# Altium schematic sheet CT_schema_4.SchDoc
size 312 x 238 mm
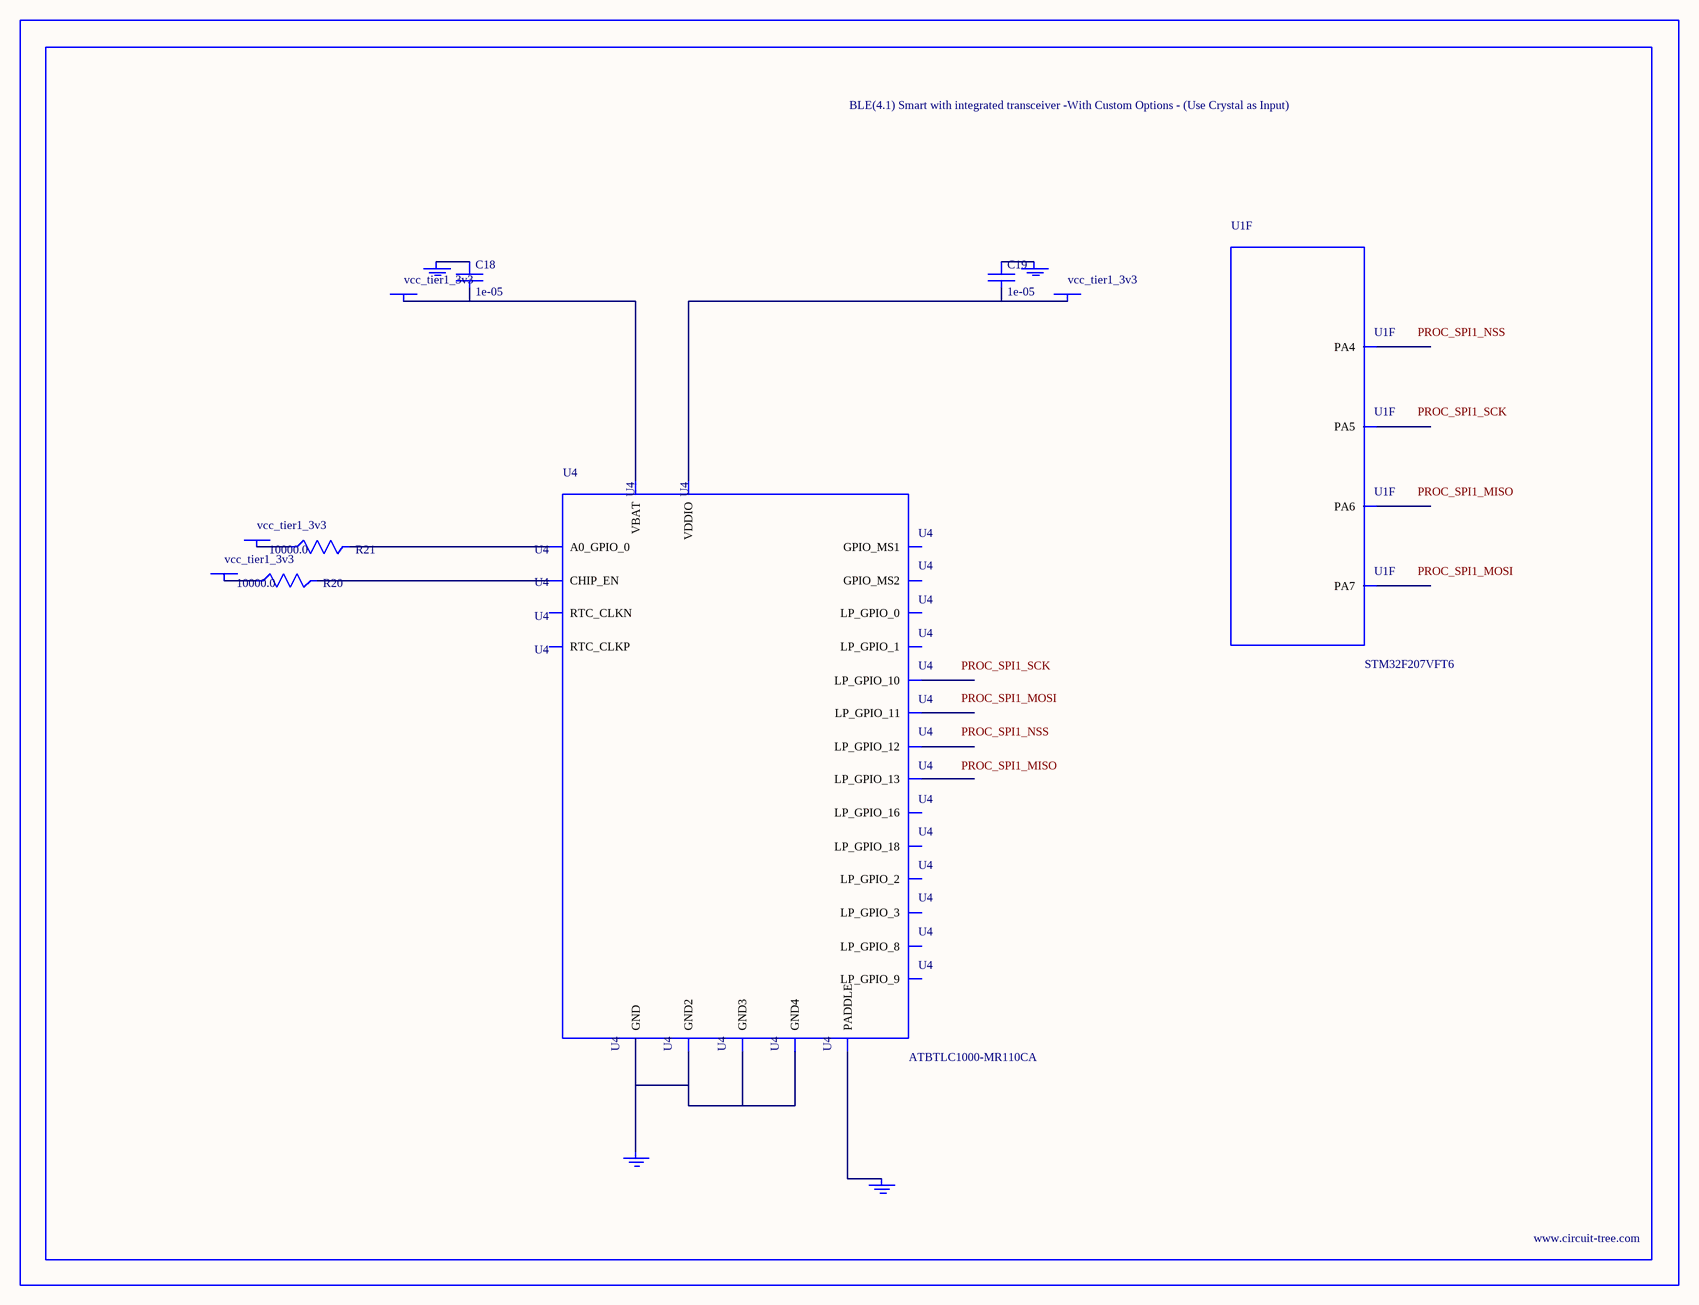
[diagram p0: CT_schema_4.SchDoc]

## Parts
BORDER3  (no value)
C18  1e-05  [C0805]
C19  1e-05  [C0805]
GND_INSTANCE_3_0  (no value)
GND_INSTANCE_3_1  (no value)
GND_INSTANCE_3_2  (no value)
GND_INSTANCE_3_3  (no value)
POWER_INSTANCE_3_0  vcc_tier1_3v3
POWER_INSTANCE_3_1  vcc_tier1_3v3
POWER_INSTANCE_3_2  vcc_tier1_3v3
POWER_INSTANCE_3_3  vcc_tier1_3v3
R20  10000.0  [R0603]
R21  10000.0  [R0603]
U1  STM32F207VFT6  [LQFP100]  (part F of 7)
U4  ATBTLC1000-MR110CA  [ATBTLC1000-MR110CA]

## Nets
NetC18_1: C18.1 GND_INSTANCE_3_0.0(GND)
NetC18_2: C18.2 POWER_INSTANCE_3_0.0(PWR) U4.6(VBAT)
NetC19_1: C19.1 GND_INSTANCE_3_1.0(GND)
NetC19_2: C19.2 POWER_INSTANCE_3_3.0(PWR) U4.22(VDDIO)
NetGND_INSTANCE_3_2_0: GND_INSTANCE_3_2.0(GND) U4.25(PADDLE)
NetGND_INSTANCE_3_3_0: GND_INSTANCE_3_3.0(GND) U4.1(GND) U4.9(GND2) U4.13(GND3) U4.24(GND4)
NetPOWER_INSTANCE_3_1_0: POWER_INSTANCE_3_1.0(PWR) R20.1
NetPOWER_INSTANCE_3_2_0: POWER_INSTANCE_3_2.0(PWR) R21.1
NetR20_2: R20.2 U4.17(CHIP_EN)
NetR21_2: R21.2 U4.20(A0_GPIO_0)

Not connected (* = marked no-connect by the designer): U1 29(PA4) 30(PA5) 31(PA6) 32(PA7); U4 2(LP_GPIO_0) 3(LP_GPIO_1) 4(LP_GPIO_2) 5(LP_GPIO_3) 7(LP_GPIO_8) 8(LP_GPIO_9) 10(LP_GPIO_10) 11(LP_GPIO_11) 12(LP_GPIO_12) 14(LP_GPIO_13) 15(GPIO_MS1) 16(GPIO_MS2) 18(RTC_CLKP) 19(RTC_CLKN) 21(LP_GPIO_16) 23(LP_GPIO_18)

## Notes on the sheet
- Labels drawn without touching a wire or pin: PROC_SPI1_MISO, PROC_SPI1_MOSI, PROC_SPI1_NSS, PROC_SPI1_SCK

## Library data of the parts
BORDER3 = BORDER_PAGE3
C18 C19 = C0805C106K8RACTU
GND_INSTANCE_3_0-GND_INSTANCE_3_3 = GND
POWER_INSTANCE_3_0-POWER_INSTANCE_3_3 = PWR
R20 R21 = RC0603JR-0710KL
